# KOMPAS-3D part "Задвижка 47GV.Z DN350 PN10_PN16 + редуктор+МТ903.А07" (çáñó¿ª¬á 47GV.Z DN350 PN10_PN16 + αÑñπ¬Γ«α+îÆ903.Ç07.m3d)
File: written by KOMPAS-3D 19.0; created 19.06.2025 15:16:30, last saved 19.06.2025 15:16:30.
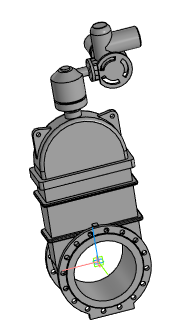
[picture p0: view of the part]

Document properties: Полное имя файла: Задвижка 47GV.Z DN350 PN10_PN16 + редуктор+МТ903.А07.a3d

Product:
- Part/product: Задвижка 47GV.Z DN350 PN10_PN16 + редуктор+МТ903.А07
    Масса: 630.089

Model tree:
1. Операция без истории:1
